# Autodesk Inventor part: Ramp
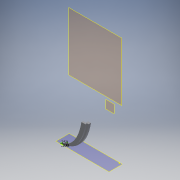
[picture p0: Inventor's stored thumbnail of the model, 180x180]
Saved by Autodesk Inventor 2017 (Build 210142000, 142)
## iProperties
Created: 2017-04
Part Number: Ramp
Material: Generic
Document SubType Name: Modeling
Designer: 1460374
Density: 1 g/cm^3
Appearance: Default
Author: 1460374
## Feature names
1. Sweep2
2. Sweep3
## Parameters: d14 = 7.62 mm, d15 = 6.35 mm, d16 = 0, d17 = 0, d18 = 0, d19 = 0
